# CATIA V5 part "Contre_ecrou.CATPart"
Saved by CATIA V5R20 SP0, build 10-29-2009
Part number: Contre_ecrou
Bounding box of the stored display mesh (mm): x -29.774 to -18.226, y 23.5 to 28.5, z -16 to -6
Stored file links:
  E:\Boulot\SeaTech\2eme ANNEE\FabricationAdditive\TP_MOSM_CREM\Projet Sauterelle de serrage\CAO Assemblage Sauterelle\Contre_ecrou.CATPart
  E:\Boulot\SeaTech\2eme ANNEE\FabricationAdditive\TP_MOSM_CREM\Projet Sauterelle de serrage\CAO Assemblage Sauterelle\Sauterelle_horizontale_05120-06.CATPart
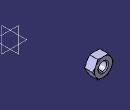
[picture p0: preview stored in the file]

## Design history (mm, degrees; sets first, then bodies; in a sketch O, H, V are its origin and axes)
Body1 (main body)
  Solid1 "05120-06_10": solid without history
